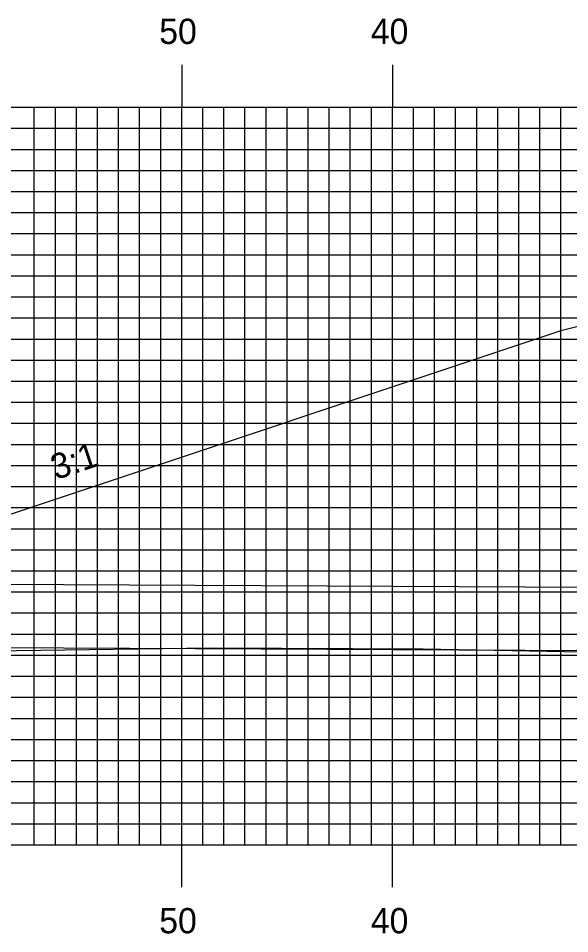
# Model space of a CAD drawing. Extents: x 1781467 to 1781810, y 442591 to 442811.
# Drawn here: x 1781574.65 to 1781600.82, y 442714.45 to 442757.88 of the extents above; entities that cross this region are included whole.
import ezdxf

# ---------------------------------------------------------------- set-up
doc = ezdxf.new("R2010")
doc.units = 0
for name, color, linetype in [('ANNOTATION', 7, 'Continuous'), ('D_Drainage_Culvert', 7, 'Continuous'), ('D_Roadway_FinishedGrade', 7, 'Continuous'), ('D_Roadway_SlopeLines', 7, 'Continuous'), ('H_V ANNOTATION', 7, 'Continuous'), ('MAJOR', 7, 'Continuous'), ('MINOR', 7, 'Continuous'), ('S_Roadway_Centerline', 7, 'Continuous')]:
    doc.layers.add(name, color=color, linetype=linetype)

msp = doc.modelspace()

# ---------------------------------------------------------------- linework, layer by layer
at = {"layer": 'D_Drainage_Culvert'}
for p, q in [((1781559.423, 442731.106), (1781707.417, 442730.343)), ((1781559.423, 442731.106), (1781707.417, 442730.343)), ((1781559.408, 442728.106), (1781707.402, 442727.343)), ((1781559.408, 442728.106), (1781707.402, 442727.343))]:
    msp.add_line(p, q, dxfattribs=at)
at = {"layer": 'D_Roadway_FinishedGrade'}
msp.add_line((1781574.647, 442734.466), (1781571.647, 442733.466), dxfattribs=at)
at = {"layer": 'D_Roadway_SlopeLines'}
msp.add_lwpolyline([(1781612.408, 442746.053), (1781600.408, 442743.053), (1781574.647, 442734.466)], dxfattribs=at)
at = {"layer": 'MAJOR'}
for p, q in [((1781582.408, 442755.669), (1781582.408, 442753.665)), ((1781592.408, 442755.669), (1781592.408, 442753.665)), ((1781492.408, 442753.665), (1781772.408, 442753.665)), ((1781492.408, 442753.665), (1781772.408, 442753.665)), ((1781582.408, 442718.665), (1781582.408, 442753.665)), ((1781592.408, 442718.665), (1781592.408, 442753.665)), ((1781492.408, 442748.665), (1781772.408, 442748.665)), ((1781492.408, 442743.665), (1781772.408, 442743.665)), ((1781492.408, 442738.665), (1781772.408, 442738.665)), ((1781492.408, 442733.665), (1781772.408, 442733.665)), ((1781492.408, 442728.665), (1781772.408, 442728.665)), ((1781492.408, 442723.665), (1781772.408, 442723.665)), ((1781492.408, 442718.665), (1781772.408, 442718.665)), ((1781492.408, 442718.665), (1781772.408, 442718.665)), ((1781582.408, 442716.661), (1781582.408, 442718.665)), ((1781592.408, 442716.661), (1781592.408, 442718.665))]:
    msp.add_line(p, q, dxfattribs=at)
at = {"layer": 'MINOR'}
for p, q in [((1781575.408, 442718.665), (1781575.408, 442753.665)), ((1781576.408, 442718.665), (1781576.408, 442753.665)), ((1781577.408, 442718.665), (1781577.408, 442753.665)), ((1781578.408, 442718.665), (1781578.408, 442753.665)), ((1781579.408, 442718.665), (1781579.408, 442753.665)), ((1781580.408, 442718.665), (1781580.408, 442753.665)), ((1781581.408, 442718.665), (1781581.408, 442753.665)), ((1781583.408, 442718.665), (1781583.408, 442753.665)), ((1781584.408, 442718.665), (1781584.408, 442753.665)), ((1781585.408, 442718.665), (1781585.408, 442753.665)), ((1781586.408, 442718.665), (1781586.408, 442753.665)), ((1781587.408, 442718.665), (1781587.408, 442753.665)), ((1781588.408, 442718.665), (1781588.408, 442753.665)), ((1781589.408, 442718.665), (1781589.408, 442753.665)), ((1781590.408, 442718.665), (1781590.408, 442753.665)), ((1781591.408, 442718.665), (1781591.408, 442753.665)), ((1781593.408, 442718.665), (1781593.408, 442753.665)), ((1781594.408, 442718.665), (1781594.408, 442753.665)), ((1781595.408, 442718.665), (1781595.408, 442753.665)), ((1781596.408, 442718.665), (1781596.408, 442753.665)), ((1781597.408, 442718.665), (1781597.408, 442753.665)), ((1781598.408, 442718.665), (1781598.408, 442753.665)), ((1781599.408, 442718.665), (1781599.408, 442753.665)), ((1781600.408, 442718.665), (1781600.408, 442753.665)), ((1781492.408, 442752.665), (1781772.408, 442752.665)), ((1781492.408, 442751.665), (1781772.408, 442751.665)), ((1781492.408, 442750.665), (1781772.408, 442750.665)), ((1781492.408, 442749.665), (1781772.408, 442749.665)), ((1781492.408, 442747.665), (1781772.408, 442747.665)), ((1781492.408, 442746.665), (1781772.408, 442746.665)), ((1781492.408, 442745.665), (1781772.408, 442745.665)), ((1781492.408, 442744.665), (1781772.408, 442744.665)), ((1781492.408, 442742.665), (1781772.408, 442742.665)), ((1781492.408, 442741.665), (1781772.408, 442741.665)), ((1781492.408, 442740.665), (1781772.408, 442740.665)), ((1781492.408, 442739.665), (1781772.408, 442739.665)), ((1781492.408, 442737.665), (1781772.408, 442737.665)), ((1781492.408, 442736.665), (1781772.408, 442736.665)), ((1781492.408, 442735.665), (1781772.408, 442735.665)), ((1781492.408, 442734.665), (1781772.408, 442734.665)), ((1781492.408, 442732.665), (1781772.408, 442732.665)), ((1781492.408, 442731.665), (1781772.408, 442731.665)), ((1781492.408, 442730.665), (1781772.408, 442730.665)), ((1781492.408, 442729.665), (1781772.408, 442729.665)), ((1781492.408, 442727.665), (1781772.408, 442727.665)), ((1781492.408, 442726.665), (1781772.408, 442726.665)), ((1781492.408, 442725.665), (1781772.408, 442725.665)), ((1781492.408, 442724.665), (1781772.408, 442724.665)), ((1781492.408, 442722.665), (1781772.408, 442722.665)), ((1781492.408, 442721.665), (1781772.408, 442721.665)), ((1781492.408, 442720.665), (1781772.408, 442720.665)), ((1781492.408, 442719.665), (1781772.408, 442719.665))]:
    msp.add_line(p, q, dxfattribs=at)
at = {"layer": 'S_Roadway_Centerline'}
msp.add_lwpolyline([(1781492.408, 442729.342), (1781498.389, 442729.01), (1781507.586, 442728.75), (1781513.832, 442728.85), (1781524.101, 442728.723), (1781527.639, 442728.582), (1781537.224, 442728.321), (1781545.64, 442728.366), (1781559.35, 442728.108), (1781569.071, 442727.794), (1781574.556, 442727.88), (1781583.781, 442728.007), (1781593.87, 442727.964), (1781606.484, 442727.726)], dxfattribs=at)

# ---------------------------------------------------------------- texts
at = {"layer": 'ANNOTATION'}
msp.add_text('3:1', height=1.2, rotation=18.4348, dxfattribs=at).set_placement((1781576.43, 442735.969))
at = {"layer": 'H_V ANNOTATION'}
for s, p in [('50', (1781581.337, 442756.665)), ('40', (1781591.38, 442756.665)), ('50', (1781581.337, 442714.465)), ('40', (1781591.38, 442714.465))]:
    msp.add_text(s, height=1.2, dxfattribs=at).set_placement(p)

doc.saveas('drawing.dxf')
